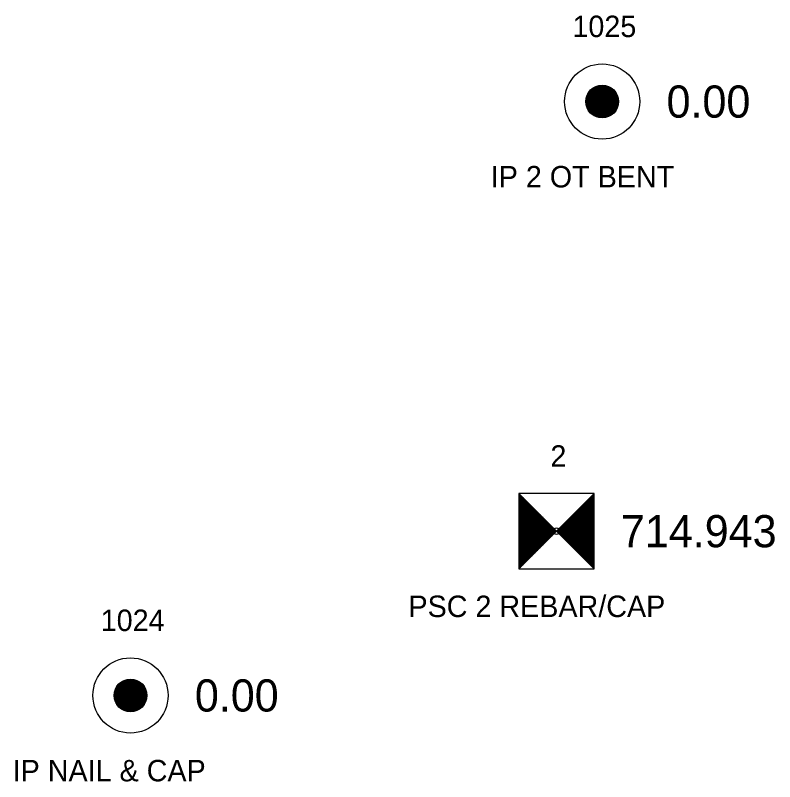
# Model space of a CAD drawing. Extents: x 1655137 to 1657928, y 1003994 to 1005407.
# Drawn here: x 1655478.6 to 1655513.97, y 1004916.94 to 1004952.63 of the extents above; entities that cross this region are included whole.
import ezdxf

# ---------------------------------------------------------------- set-up
doc = ezdxf.new("R2010")
doc.units = 0
for name, color, linetype in [('RD_EX_DV_Prop_txCode', 7, 'Continuous'), ('RD_EX_DV_PropPin', 7, 'Continuous'), ('RD_EX_TX_DV_Prop_ELEV', 7, 'Continuous'), ('RD_HC_Survey', 7, 'Continuous'), ('RD_HC_Survey_ELEV', 7, 'Continuous'), ('RD_HC_txCode', 7, 'Continuous'), ('RD_SMD_Locator', 7, 'Continuous')]:
    doc.layers.add(name, color=color, linetype=linetype)

msp = doc.modelspace()

# ---------------------------------------------------------------- linework, layer by layer
at = {"layer": 'RD_EX_DV_PropPin'}
for p, q in [((1655505.443, 1004948.03), (1655505.443, 1004949.194)), ((1655505.478, 1004948.002), (1655505.478, 1004949.222)), ((1655505.513, 1004947.978), (1655505.513, 1004949.247)), ((1655505.548, 1004947.956), (1655505.548, 1004949.269)), ((1655505.583, 1004947.937), (1655505.583, 1004949.288)), ((1655505.618, 1004947.919), (1655505.618, 1004949.305)), ((1655505.653, 1004947.905), (1655505.653, 1004949.32)), ((1655505.688, 1004947.892), (1655505.688, 1004949.333)), ((1655505.723, 1004947.881), (1655505.723, 1004949.344)), ((1655505.758, 1004947.872), (1655505.758, 1004949.353)), ((1655505.793, 1004947.864), (1655505.793, 1004949.36)), ((1655505.828, 1004947.858), (1655505.828, 1004949.366)), ((1655505.863, 1004947.854), (1655505.863, 1004949.37)), ((1655505.898, 1004947.852), (1655505.898, 1004949.372)), ((1655505.933, 1004947.851), (1655505.933, 1004949.373)), ((1655505.968, 1004947.852), (1655505.968, 1004949.372)), ((1655506.003, 1004947.854), (1655506.003, 1004949.37)), ((1655506.038, 1004947.858), (1655506.038, 1004949.366)), ((1655506.073, 1004947.864), (1655506.073, 1004949.36)), ((1655506.108, 1004947.872), (1655506.108, 1004949.353)), ((1655506.143, 1004947.881), (1655506.143, 1004949.344)), ((1655506.178, 1004947.892), (1655506.178, 1004949.333)), ((1655506.213, 1004947.905), (1655506.213, 1004949.32)), ((1655506.248, 1004947.919), (1655506.248, 1004949.305)), ((1655506.283, 1004947.937), (1655506.283, 1004949.288)), ((1655506.318, 1004947.956), (1655506.318, 1004949.269)), ((1655506.353, 1004947.978), (1655506.353, 1004949.247)), ((1655506.388, 1004948.002), (1655506.388, 1004949.222)), ((1655506.423, 1004948.03), (1655506.423, 1004949.194)), ((1655505.233, 1004948.314), (1655505.233, 1004948.91)), ((1655505.268, 1004948.243), (1655505.268, 1004948.982)), ((1655505.303, 1004948.186), (1655505.303, 1004949.039)), ((1655505.338, 1004948.138), (1655505.338, 1004949.086)), ((1655505.373, 1004948.097), (1655505.373, 1004949.127)), ((1655505.408, 1004948.061), (1655505.408, 1004949.163)), ((1655506.458, 1004948.061), (1655506.458, 1004949.163)), ((1655506.493, 1004948.097), (1655506.493, 1004949.127)), ((1655506.528, 1004948.138), (1655506.528, 1004949.086)), ((1655506.563, 1004948.186), (1655506.563, 1004949.039)), ((1655506.598, 1004948.243), (1655506.598, 1004948.982)), ((1655506.633, 1004948.314), (1655506.633, 1004948.91)), ((1655505.198, 1004948.416), (1655505.198, 1004948.808)), ((1655506.668, 1004948.416), (1655506.668, 1004948.808)), ((1655483.856, 1004920.199), (1655483.856, 1004921.706)), ((1655483.891, 1004920.195), (1655483.891, 1004921.71)), ((1655483.926, 1004920.192), (1655483.926, 1004921.713)), ((1655483.961, 1004920.192), (1655483.961, 1004921.714)), ((1655483.996, 1004920.192), (1655483.996, 1004921.713)), ((1655484.031, 1004920.195), (1655484.031, 1004921.71)), ((1655484.066, 1004920.199), (1655484.066, 1004921.706)), ((1655483.331, 1004920.526), (1655483.331, 1004921.379)), ((1655483.366, 1004920.479), (1655483.366, 1004921.427)), ((1655483.401, 1004920.438), (1655483.401, 1004921.468)), ((1655483.436, 1004920.402), (1655483.436, 1004921.503)), ((1655483.471, 1004920.371), (1655483.471, 1004921.535)), ((1655483.506, 1004920.343), (1655483.506, 1004921.563)), ((1655483.541, 1004920.318), (1655483.541, 1004921.587)), ((1655483.576, 1004920.296), (1655483.576, 1004921.609)), ((1655483.611, 1004920.277), (1655483.611, 1004921.628)), ((1655483.646, 1004920.26), (1655483.646, 1004921.645)), ((1655483.681, 1004920.245), (1655483.681, 1004921.66)), ((1655483.716, 1004920.232), (1655483.716, 1004921.673)), ((1655483.751, 1004920.221), (1655483.751, 1004921.684)), ((1655483.786, 1004920.212), (1655483.786, 1004921.693)), ((1655483.821, 1004920.205), (1655483.821, 1004921.701)), ((1655484.101, 1004920.205), (1655484.101, 1004921.701)), ((1655484.136, 1004920.212), (1655484.136, 1004921.693)), ((1655484.171, 1004920.221), (1655484.171, 1004921.684)), ((1655484.206, 1004920.232), (1655484.206, 1004921.673)), ((1655484.241, 1004920.245), (1655484.241, 1004921.66)), ((1655484.276, 1004920.26), (1655484.276, 1004921.645)), ((1655484.311, 1004920.277), (1655484.311, 1004921.628)), ((1655484.346, 1004920.296), (1655484.346, 1004921.609)), ((1655484.381, 1004920.318), (1655484.381, 1004921.587)), ((1655484.416, 1004920.343), (1655484.416, 1004921.563)), ((1655484.451, 1004920.371), (1655484.451, 1004921.535)), ((1655484.486, 1004920.402), (1655484.486, 1004921.503)), ((1655484.521, 1004920.438), (1655484.521, 1004921.468)), ((1655484.556, 1004920.479), (1655484.556, 1004921.427)), ((1655484.591, 1004920.526), (1655484.591, 1004921.379)), ((1655483.226, 1004920.757), (1655483.226, 1004921.149)), ((1655483.261, 1004920.655), (1655483.261, 1004921.251)), ((1655483.296, 1004920.583), (1655483.296, 1004921.322)), ((1655484.626, 1004920.583), (1655484.626, 1004921.322)), ((1655484.661, 1004920.655), (1655484.661, 1004921.251)), ((1655484.696, 1004920.757), (1655484.696, 1004921.149))]:
    msp.add_line(p, q, dxfattribs=at)
for centre, radius in [((1655505.933, 1004948.612), 1.75), ((1655505.933, 1004948.612), 0.761), ((1655483.961, 1004920.953), 1.75), ((1655483.961, 1004920.953), 0.761)]:
    msp.add_circle(centre, radius, dxfattribs=at)
at = {"layer": 'RD_HC_Survey'}
for p, q in [((1655502.057, 1004930.354), (1655505.557, 1004926.854)), ((1655505.557, 1004930.354), (1655502.057, 1004926.854)), ((1655502.081, 1004930.329), (1655502.081, 1004926.879)), ((1655502.106, 1004930.304), (1655502.106, 1004926.903)), ((1655502.131, 1004930.28), (1655502.131, 1004926.928)), ((1655505.482, 1004930.28), (1655505.482, 1004926.928)), ((1655505.507, 1004930.304), (1655505.507, 1004926.903)), ((1655505.532, 1004930.329), (1655505.532, 1004926.879)), ((1655502.156, 1004930.255), (1655502.156, 1004926.953)), ((1655502.18, 1004930.23), (1655502.18, 1004926.978)), ((1655502.205, 1004930.205), (1655502.205, 1004927.002)), ((1655502.23, 1004930.181), (1655502.23, 1004927.027)), ((1655502.255, 1004930.156), (1655502.255, 1004927.052)), ((1655502.279, 1004930.131), (1655502.279, 1004927.077)), ((1655502.304, 1004930.106), (1655502.304, 1004927.101)), ((1655502.329, 1004930.082), (1655502.329, 1004927.126)), ((1655502.354, 1004930.057), (1655502.354, 1004927.151)), ((1655502.378, 1004930.032), (1655502.378, 1004927.176)), ((1655502.403, 1004930.007), (1655502.403, 1004927.2)), ((1655502.428, 1004929.983), (1655502.428, 1004927.225)), ((1655502.453, 1004929.958), (1655502.453, 1004927.25)), ((1655502.477, 1004929.933), (1655502.477, 1004927.275)), ((1655505.136, 1004929.933), (1655505.136, 1004927.275)), ((1655505.161, 1004929.958), (1655505.161, 1004927.25)), ((1655505.185, 1004929.983), (1655505.185, 1004927.225)), ((1655505.21, 1004930.007), (1655505.21, 1004927.2)), ((1655505.235, 1004930.032), (1655505.235, 1004927.176)), ((1655505.26, 1004930.057), (1655505.26, 1004927.151)), ((1655505.284, 1004930.082), (1655505.284, 1004927.126)), ((1655505.309, 1004930.106), (1655505.309, 1004927.101)), ((1655505.334, 1004930.131), (1655505.334, 1004927.077)), ((1655505.359, 1004930.156), (1655505.359, 1004927.052)), ((1655505.383, 1004930.181), (1655505.383, 1004927.027)), ((1655505.408, 1004930.205), (1655505.408, 1004927.002)), ((1655505.433, 1004930.23), (1655505.433, 1004926.978)), ((1655505.458, 1004930.255), (1655505.458, 1004926.953)), ((1655502.502, 1004929.908), (1655502.502, 1004927.299)), ((1655502.527, 1004929.884), (1655502.527, 1004927.324)), ((1655502.552, 1004929.859), (1655502.552, 1004927.349)), ((1655502.576, 1004929.834), (1655502.576, 1004927.374)), ((1655502.601, 1004929.809), (1655502.601, 1004927.398)), ((1655502.626, 1004929.785), (1655502.626, 1004927.423)), ((1655502.651, 1004929.76), (1655502.651, 1004927.448)), ((1655502.675, 1004929.735), (1655502.675, 1004927.473)), ((1655502.7, 1004929.71), (1655502.7, 1004927.497)), ((1655502.725, 1004929.686), (1655502.725, 1004927.522)), ((1655502.75, 1004929.661), (1655502.75, 1004927.547)), ((1655502.774, 1004929.636), (1655502.774, 1004927.572)), ((1655502.799, 1004929.611), (1655502.799, 1004927.596)), ((1655502.824, 1004929.587), (1655502.824, 1004927.621)), ((1655502.849, 1004929.562), (1655502.849, 1004927.646)), ((1655504.765, 1004929.562), (1655504.765, 1004927.646)), ((1655504.789, 1004929.587), (1655504.789, 1004927.621)), ((1655504.814, 1004929.611), (1655504.814, 1004927.596)), ((1655504.839, 1004929.636), (1655504.839, 1004927.572)), ((1655504.864, 1004929.661), (1655504.864, 1004927.547)), ((1655504.888, 1004929.686), (1655504.888, 1004927.522)), ((1655504.913, 1004929.71), (1655504.913, 1004927.497)), ((1655504.938, 1004929.735), (1655504.938, 1004927.473)), ((1655504.963, 1004929.76), (1655504.963, 1004927.448)), ((1655504.987, 1004929.785), (1655504.987, 1004927.423)), ((1655505.012, 1004929.809), (1655505.012, 1004927.398)), ((1655505.037, 1004929.834), (1655505.037, 1004927.374)), ((1655505.062, 1004929.859), (1655505.062, 1004927.349)), ((1655505.086, 1004929.884), (1655505.086, 1004927.324)), ((1655505.111, 1004929.908), (1655505.111, 1004927.299)), ((1655502.873, 1004929.537), (1655502.873, 1004927.671)), ((1655502.898, 1004929.512), (1655502.898, 1004927.695)), ((1655502.923, 1004929.488), (1655502.923, 1004927.72)), ((1655502.948, 1004929.463), (1655502.948, 1004927.745)), ((1655502.972, 1004929.438), (1655502.972, 1004927.77)), ((1655502.997, 1004929.413), (1655502.997, 1004927.794)), ((1655503.022, 1004929.389), (1655503.022, 1004927.819)), ((1655503.047, 1004929.364), (1655503.047, 1004927.844)), ((1655503.071, 1004929.339), (1655503.071, 1004927.869)), ((1655503.096, 1004929.314), (1655503.096, 1004927.893)), ((1655503.121, 1004929.29), (1655503.121, 1004927.918)), ((1655503.146, 1004929.265), (1655503.146, 1004927.943)), ((1655503.17, 1004929.24), (1655503.17, 1004927.967)), ((1655503.195, 1004929.215), (1655503.195, 1004927.992)), ((1655504.418, 1004929.215), (1655504.418, 1004927.992)), ((1655504.443, 1004929.24), (1655504.443, 1004927.967)), ((1655504.468, 1004929.265), (1655504.468, 1004927.943)), ((1655504.492, 1004929.29), (1655504.492, 1004927.918)), ((1655504.517, 1004929.314), (1655504.517, 1004927.893)), ((1655504.542, 1004929.339), (1655504.542, 1004927.869)), ((1655504.567, 1004929.364), (1655504.567, 1004927.844)), ((1655504.591, 1004929.389), (1655504.591, 1004927.819)), ((1655504.616, 1004929.413), (1655504.616, 1004927.794)), ((1655504.641, 1004929.438), (1655504.641, 1004927.77)), ((1655504.666, 1004929.463), (1655504.666, 1004927.745)), ((1655504.69, 1004929.488), (1655504.69, 1004927.72)), ((1655504.715, 1004929.512), (1655504.715, 1004927.695)), ((1655504.74, 1004929.537), (1655504.74, 1004927.671)), ((1655503.22, 1004929.191), (1655503.22, 1004928.017)), ((1655503.245, 1004929.166), (1655503.245, 1004928.042)), ((1655503.269, 1004929.141), (1655503.269, 1004928.066)), ((1655503.294, 1004929.116), (1655503.294, 1004928.091)), ((1655503.319, 1004929.092), (1655503.319, 1004928.116)), ((1655503.344, 1004929.067), (1655503.344, 1004928.141)), ((1655503.368, 1004929.042), (1655503.368, 1004928.165)), ((1655503.393, 1004929.017), (1655503.393, 1004928.19)), ((1655503.418, 1004928.993), (1655503.418, 1004928.215)), ((1655503.443, 1004928.968), (1655503.443, 1004928.24)), ((1655503.467, 1004928.943), (1655503.467, 1004928.264)), ((1655503.492, 1004928.918), (1655503.492, 1004928.289)), ((1655503.517, 1004928.894), (1655503.517, 1004928.314)), ((1655503.542, 1004928.869), (1655503.542, 1004928.339)), ((1655503.566, 1004928.844), (1655503.566, 1004928.363)), ((1655504.047, 1004928.844), (1655504.047, 1004928.363)), ((1655504.072, 1004928.869), (1655504.072, 1004928.339)), ((1655504.096, 1004928.894), (1655504.096, 1004928.314)), ((1655504.121, 1004928.918), (1655504.121, 1004928.289)), ((1655504.146, 1004928.943), (1655504.146, 1004928.264)), ((1655504.171, 1004928.968), (1655504.171, 1004928.24)), ((1655504.195, 1004928.993), (1655504.195, 1004928.215)), ((1655504.22, 1004929.017), (1655504.22, 1004928.19)), ((1655504.245, 1004929.042), (1655504.245, 1004928.165)), ((1655504.27, 1004929.067), (1655504.27, 1004928.141)), ((1655504.294, 1004929.092), (1655504.294, 1004928.116)), ((1655504.319, 1004929.116), (1655504.319, 1004928.091)), ((1655504.344, 1004929.141), (1655504.344, 1004928.066)), ((1655504.369, 1004929.166), (1655504.369, 1004928.042)), ((1655504.393, 1004929.191), (1655504.393, 1004928.017)), ((1655503.591, 1004928.819), (1655503.591, 1004928.388)), ((1655503.616, 1004928.795), (1655503.616, 1004928.413)), ((1655503.641, 1004928.77), (1655503.641, 1004928.438)), ((1655503.665, 1004928.745), (1655503.665, 1004928.462)), ((1655503.69, 1004928.72), (1655503.69, 1004928.487)), ((1655503.715, 1004928.696), (1655503.715, 1004928.512)), ((1655503.74, 1004928.671), (1655503.74, 1004928.537)), ((1655503.764, 1004928.646), (1655503.764, 1004928.561)), ((1655503.789, 1004928.621), (1655503.789, 1004928.586)), ((1655503.824, 1004928.621), (1655503.824, 1004928.586)), ((1655503.849, 1004928.646), (1655503.849, 1004928.561)), ((1655503.874, 1004928.671), (1655503.874, 1004928.537)), ((1655503.898, 1004928.696), (1655503.898, 1004928.512)), ((1655503.923, 1004928.72), (1655503.923, 1004928.487)), ((1655503.948, 1004928.745), (1655503.948, 1004928.462)), ((1655503.973, 1004928.77), (1655503.973, 1004928.438)), ((1655503.997, 1004928.795), (1655503.997, 1004928.413)), ((1655504.022, 1004928.819), (1655504.022, 1004928.388))]:
    msp.add_line(p, q, dxfattribs=at)
msp.add_lwpolyline([(1655505.557, 1004930.354), (1655502.057, 1004930.354), (1655502.057, 1004926.854), (1655505.557, 1004926.854)], close=True, dxfattribs=at)
at = {"layer": 'RD_SMD_Locator'}
for centre in [(1655505.933, 1004948.612), (1655503.807, 1004928.604), (1655483.961, 1004920.953)]:
    msp.add_circle(centre, 0.15, dxfattribs=at)

# ---------------------------------------------------------------- texts
at = {"layer": 'RD_EX_DV_Prop_txCode'}
for s, p in [('1025', (1655504.547, 1004951.612)), ('IP 2 OT BENT', (1655500.744, 1004944.612)), ('1024', (1655482.575, 1004923.953)), ('IP NAIL & CAP', (1655478.473, 1004916.953))]:
    msp.add_text(s, height=1, dxfattribs=at).set_placement(p)
at = {"layer": 'RD_EX_TX_DV_Prop_ELEV'}
for p in [(1655508.933, 1004947.862), (1655486.961, 1004920.203)]:
    msp.add_text('0.00', height=1.5, dxfattribs=at).set_placement(p)
at = {"layer": 'RD_HC_Survey_ELEV'}
msp.add_text('714.943', height=1.5, dxfattribs=at).set_placement((1655506.807, 1004927.854))
at = {"layer": 'RD_HC_txCode'}
for s, p in [('2', (1655503.523, 1004931.604)), ('PSC 2 REBAR/CAP', (1655496.909, 1004924.604))]:
    msp.add_text(s, height=1, dxfattribs=at).set_placement(p)

doc.saveas('drawing.dxf')
